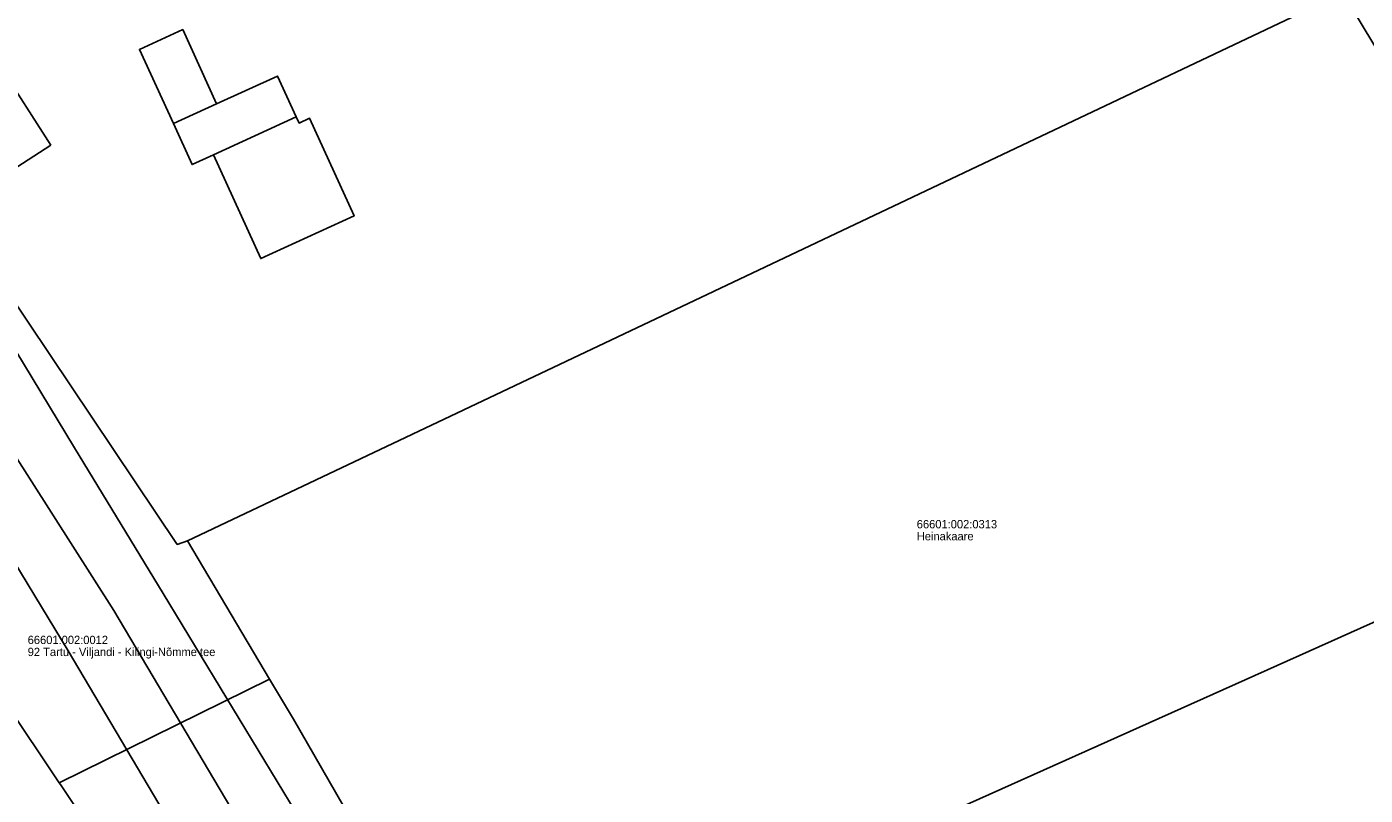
# Model space of a CAD drawing. Extents: x 626224 to 628280, y 6467750 to 6471135.
# Drawn here: x 627790 to 627935, y 6468470.2 to 6468553.4 of the extents above; entities that cross this region are included whole.
import ezdxf

# ---------------------------------------------------------------- set-up
doc = ezdxf.new("R2010")
doc.units = 0
for name, color, linetype in [('Hoone Elu- või ühiskondlik hoone', 7, 'Continuous'), ('Hoone Kõrval- või tootmishoone', 7, 'Continuous'), ('PIIR', 7, 'Continuous'), ('Tee Liiklusala', 7, 'Continuous'), ('Tee Põhimaantee Püsikate', 7, 'Continuous')]:
    doc.layers.add(name, color=color, linetype=linetype)

msp = doc.modelspace()

# ---------------------------------------------------------------- linework, layer by layer
at = {"layer": 'Hoone Elu- või ühiskondlik hoone'}
msp.add_lwpolyline([(627819.21, 6468543.65), (627819.52, 6468542.98), (627820.65, 6468543.5), (627825.48, 6468532.93), (627815.37, 6468528.31), (627810.24, 6468539.55)], close=True, dxfattribs=at)
at = {"layer": 'Hoone Kõrval- või tootmishoone'}
for points in [[(627810.59, 6468545.06), (627805.91, 6468542.92), (627802.23, 6468550.96), (627806.92, 6468553.1)], [(627792.64, 6468540.6), (627786.44, 6468536.6), (627780.81, 6468545.33), (627787.01, 6468549.33)], [(627819.21, 6468543.65), (627810.24, 6468539.55), (627807.93, 6468538.49), (627805.91, 6468542.92), (627810.59, 6468545.06), (627817.19, 6468548.07)]]:
    msp.add_lwpolyline(points, close=True, dxfattribs=at)
at = {"layer": 'PIIR'}
for points in [[(627865.5, 6468668.3), (627932.6, 6468557.07), (627807.45, 6468497.75), (627806.32, 6468497.36), (627739.66, 6468596.76)], [(627932.6, 6468557.07), (627965.68, 6468502.25), (627838.09, 6468445.14), (627818.92, 6468478.42), (627816.33, 6468482.77), (627807.45, 6468497.75)], [(627796.62, 6468466.91), (627730.26, 6468443.18), (627664.7, 6468422.83), (627644.76, 6468421.52), (627633.52, 6468445.58), (627608.44, 6468499.25), (627666.94, 6468517.08), (627746.91, 6468541.23), (627793.54, 6468471.56), (627793.68, 6468471.35)], [(627965.68, 6468502.25), (628025.29, 6468403.44), (627924.44, 6468351.42), (627930.15, 6468335.32), (627893.5, 6468317.49), (627836.88, 6468444.6), (627838.09, 6468445.14)]]:
    msp.add_lwpolyline(points, close=True, dxfattribs=at)
for points in [[(627739.66, 6468596.76), (627806.32, 6468497.36), (627807.45, 6468497.75), (627816.33, 6468482.77), (627793.54, 6468471.56), (627746.91, 6468541.23), (627688.18, 6468626.77)], [(627869.05, 6468319.44), (627860.61, 6468341.12), (627850.92, 6468363.47), (627843.3, 6468381.02), (627834.21, 6468400.21), (627826.02, 6468416.53), (627816.81, 6468434.6), (627809.58, 6468448), (627801.28, 6468461.34), (627796.62, 6468466.91), (627793.68, 6468471.35), (627793.54, 6468471.56), (627816.33, 6468482.77), (627818.92, 6468478.42), (627838.09, 6468445.14), (627836.88, 6468444.6), (627893.5, 6468317.49)]]:
    msp.add_lwpolyline(points, dxfattribs=at)
at = {"layer": 'Tee Liiklusala'}
for points in [[(628004.71, 6467966.98), (627997.81, 6467987.98), (627990.14, 6468009.25), (627982.43, 6468031.57), (627970.39, 6468066.34), (627943.56, 6468142.05), (627938.77, 6468155.66), (627916.35, 6468218.79), (627896.06, 6468271.56), (627889.69, 6468286.93), (627880.37, 6468309.48), (627875.6, 6468321.93), (627863.15, 6468354.49), (627844.06, 6468395.68), (627818.98, 6468444.86), (627806.07, 6468466.34), (627794.52, 6468485.83), (627778.37, 6468512.41), (627770.48, 6468525.39), (627740.56, 6468568.76)], [(627760.92, 6468560.36), (627780.56, 6468531.91), (627795.19, 6468507.83), (627804.8, 6468492.03), (627819.21, 6468468.28), (627829.48, 6468450.66), (627842.63, 6468424.88), (627852.37, 6468405.79), (627854.86, 6468400.94), (627874.21, 6468359.17), (627891.81, 6468313.11), (627897.89, 6468298.46), (627907.18, 6468276.08), (627914.22, 6468258.33), (627924.31, 6468232.91), (627926.05, 6468227.94), (627930.17, 6468216.22), (627939.76, 6468188.97), (627954.88, 6468146.07), (627973.91, 6468092.36), (627984.64, 6468061.12)]]:
    msp.add_lwpolyline(points, dxfattribs=at)
at = {"layer": 'Tee Põhimaantee Püsikate'}
msp.add_lwpolyline([(627700.9, 6468634.14), (627743.45, 6468575.1), (627775.1, 6468528.3), (627799.45, 6468490.21), (627812.12, 6468468.85)], dxfattribs=at)

# ---------------------------------------------------------------- texts
at = {"layer": 'PIIR'}
for s, p in [('66601:002:0313', (627886.43, 6468499.1)), ('Heinakaare', (627886.43, 6468497.8)), ('66601:002:0012', (627790.12, 6468486.57)), ('92 Tartu - Viljandi - Kilingi-Nõmme tee', (627790.12, 6468485.27))]:
    msp.add_text(s, height=0.9, dxfattribs=at).set_placement(p)

doc.saveas('drawing.dxf')
